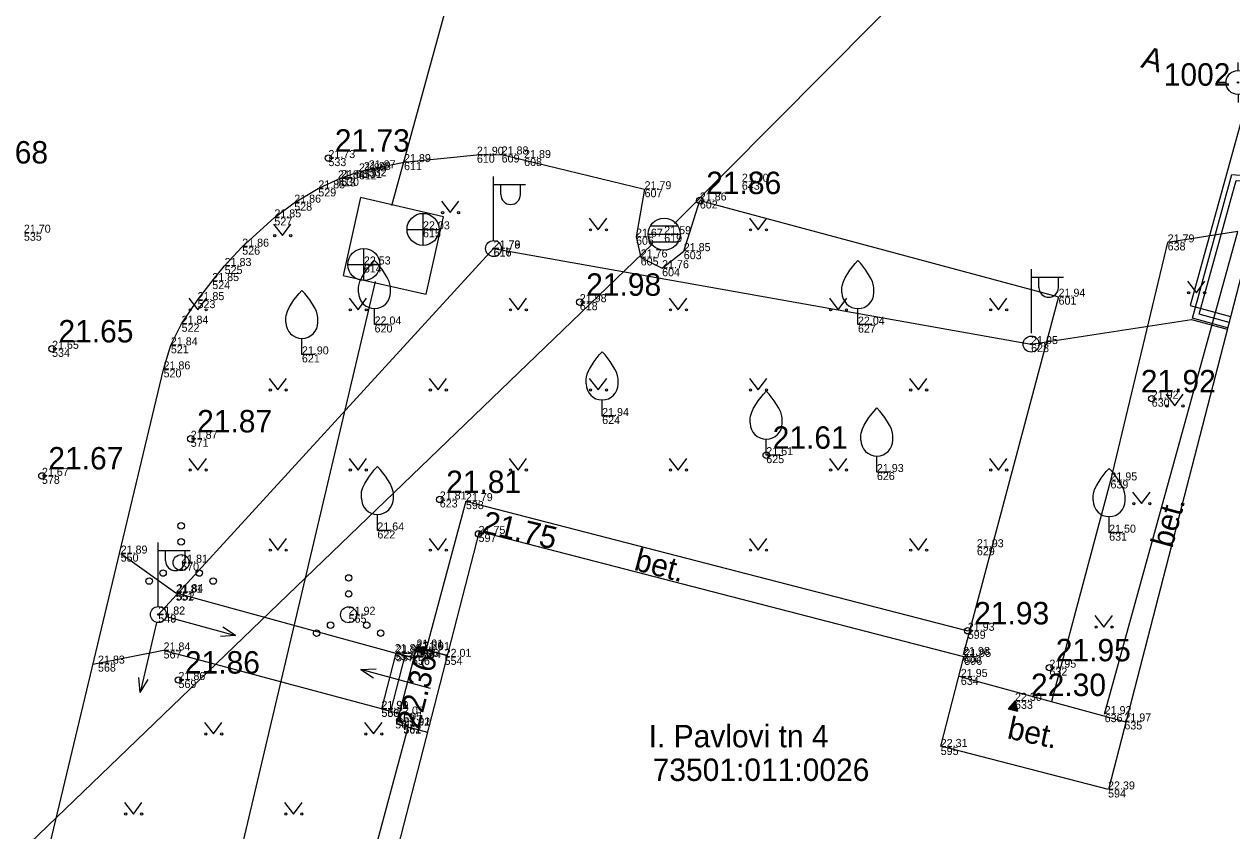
# Model space of a CAD drawing. Extents: x 714279 to 714471, y 6589851 to 6590083.
# Drawn here: x 714335.18 to 714372.9, y 6590005.81 to 6590030.99 of the extents above; entities that cross this region are included whole.
import ezdxf

# ---------------------------------------------------------------- set-up
doc = ezdxf.new("R2010")
doc.units = 0
for name, color, linetype in [('ALUSVORK', 7, 'Continuous'), ('HALJASTUS', 7, 'Continuous'), ('HOONE', 7, 'Continuous'), ('HOONEDET', 7, 'Continuous'), ('KKAEV', 7, 'Continuous'), ('KORGUS', 7, 'Continuous'), ('MOOTKORG', 7, 'Continuous'), ('MOOTMPUNKT', 7, 'Continuous'), ('MPKAABEL', 7, 'Continuous'), ('MPOHULIIN', 7, 'Continuous'), ('PIIR', 7, 'Continuous'), ('POST', 7, 'Continuous'), ('PUU', 7, 'Continuous'), ('SITRASS', 7, 'Continuous'), ('SKKAEV', 7, 'Continuous'), ('SKTRASS', 7, 'Continuous'), ('TEE', 7, 'Continuous'), ('TTRASS', 7, 'Continuous')]:
    doc.layers.add(name, color=color, linetype=linetype)

# ---------------------------------------------------------------- blocks, each defined once
blk = doc.blocks.new('SPYMAR')
at = {"layer": 'ALUSVORK'}
for p, q in [((0, 0.75), (0, 1.25)), ((-0.75, 0), (-1.25, 0)), ((0.75, 0), (1.25, 0)), ((0, -0.75), (0, -1.25))]:
    blk.add_line(p, q, dxfattribs=at)
for radius in [0.75, 0.044]:
    blk.add_circle((0, 0), radius, dxfattribs=at)
blk = doc.blocks.new('RING02')
at = {"layer": 'KORGUS'}
blk.add_circle((0, 0), 0.2, dxfattribs=at)
blk = doc.blocks.new('BEPOST')
at = {"layer": 'POST'}
for radius in [0.5, 0.0467]:
    blk.add_circle((0, 0), radius, dxfattribs=at)
blk = doc.blocks.new('POINT_DISPLAY')
blk.add_line((0, 0), (0, 0))
blk = doc.blocks.new('VAPOST')
at = {"layer": 'POST'}
for p, q in [((0, 0.5), (0, 4.5)), ((0, 4), (2, 4)), ((0.453, 3.358), (0.453, 4)), ((1.679, 3.358), (1.679, 4))]:
    blk.add_line(p, q, dxfattribs=at)
blk.add_arc((1.066, 3.358), 0.613, 180, 0, dxfattribs=at)
blk.add_blockref('POINT_DISPLAY', (0, 0), dxfattribs=at)
blk = doc.blocks.new('RTKQRG')
at = {"layer": 'HOONEDET'}
for p, q in [((0, 0), (-0.49, 0.97)), ((0.49, 0.97), (-0.49, 0.97)), ((-0.48, 0.94), (0.21, 0.42)), ((-0.44, 0.97), (0.23, 0.46)), ((-0.42, 0.84), (0.19, 0.37)), ((-0.37, 0.74), (0.17, 0.33)), ((-0.35, 0.97), (0.26, 0.51)), ((-0.32, 0.63), (0.14, 0.28)), ((-0.27, 0.97), (0.28, 0.55)), ((-0.27, 0.53), (0.12, 0.24)), ((-0.22, 0.43), (0.1, 0.19)), ((-0.19, 0.97), (0.3, 0.6)), ((-0.17, 0.33), (0.07, 0.15)), ((-0.11, 0.97), (0.33, 0.64)), ((-0.11, 0.22), (0.05, 0.1)), ((-0.06, 0.12), (0.03, 0.05)), ((-0.02, 0.97), (0.35, 0.69)), ((-0.01, 0.02), (0, 0.01)), ((0, 0), (0.49, 0.97)), ((0.06, 0.97), (0.37, 0.73)), ((0.14, 0.97), (0.39, 0.78)), ((0.22, 0.97), (0.42, 0.83)), ((0.31, 0.97), (0.44, 0.87)), ((0.39, 0.97), (0.46, 0.92)), ((0.47, 0.97), (0.49, 0.96))]:
    blk.add_line(p, q, dxfattribs=at)
blk = doc.blocks.new('VQSA')
at = {"layer": 'HALJASTUS'}
for centre, radius in [((0, 2.3), 0.2), ((0, 1.3), 0.2), ((0, 0), 0.5), ((-1.13, -0.65), 0.2), ((1.13, -0.65), 0.2), ((-2, -1.15), 0.2), ((2, -1.15), 0.2)]:
    blk.add_circle(centre, radius, dxfattribs=at)
blk = doc.blocks.new('KAKAEV')
at = {"layer": 'KKAEV'}
for p, q in [((0, -1), (0, 1)), ((-1, 0), (1, 0))]:
    blk.add_line(p, q, dxfattribs=at)
blk.add_circle((0, 0), 1, dxfattribs=at)
blk = doc.blocks.new('REKAEV')
at = {"layer": 'SKKAEV'}
for p, q in [((0.86, 0.5), (-0.86, 0.5)), ((-1, 0), (1, 0)), ((0.86, -0.5), (-0.86, -0.5))]:
    blk.add_line(p, q, dxfattribs=at)
blk.add_circle((0, 0), 1, dxfattribs=at)
blk = doc.blocks.new('VILJA1')
at = {"layer": 'PUU'}
for p, q in [((0, 0), (0, 1)), ((0.8, 0), (0, 0))]:
    blk.add_line(p, q, dxfattribs=at)
for points in [[(-1, 2), (-1, 2.3), (-0.98, 2.43), (-0.91, 2.69), (-0.79, 2.93), (-0.5, 3.4), (-0.18, 3.81), (0, 4)], [(1, 2), (1, 2.3), (0.98, 2.43), (0.91, 2.69), (0.79, 2.93), (0.5, 3.4), (0.18, 3.81), (0, 4)]]:
    blk.add_lwpolyline(points, dxfattribs=at)
blk.add_arc((0, 2), 1, 180, 0, dxfattribs=at)
blk = doc.blocks.new('MPSUUN')
at = {"layer": 'MPOHULIIN'}
for p, q in [((0.5, 0), (5, 0)), ((5, 0), (4.097, -0.297)), ((5, 0), (4.098, 0.3))]:
    blk.add_line(p, q, dxfattribs=at)
blk.add_blockref('POINT_DISPLAY', (0, 0), dxfattribs=at)
blk = doc.blocks.new('MURU_1')
at = {"layer": 'HALJASTUS'}
for p, q in [((-0.93, 1.21), (0, 0)), ((0, 0), (0.89, 1.21))]:
    blk.add_line(p, q, dxfattribs=at)
for centre in [(-0.8, 0), (0.86, 0)]:
    blk.add_circle(centre, 0.11, dxfattribs=at)

msp = doc.modelspace()

# ---------------------------------------------------------------- linework, layer by layer
at = {"layer": 'HOONE'}
for points in [[(714368.084, 6590003.497), (714362.833, 6589983.153), (714366.948, 6589982.091), (714366.479, 6589980.273), (714368.704, 6589979.699), (714369.168, 6589981.497), (714375.054, 6589979.978), (714385.707, 6590021.254), (714379.88, 6590022.758), (714380.346, 6590024.563), (714378.09, 6590025.145), (714377.63, 6590023.366), (714373.521, 6590024.426), (714369.05, 6590007.103), (714363.815, 6590008.455), (714364.534, 6590011.243), (714349.394, 6590015.151), (714346.235, 6590002.913), (714361.396, 6589999), (714362.901, 6590004.835), (714368.084, 6590003.497)], [(714347.349, 6590011.208), (714346.794, 6590011.353), (714346.34, 6590009.617), (714346.895, 6590009.472)], [(714347.075, 6590011.28), (714346.621, 6590009.544)], [(714346.794, 6590011.353), (714347.349, 6590011.208), (714347.434, 6590011.532), (714348.395, 6590011.281)], [(714348.395, 6590011.281), (714347.434, 6590011.532), (714346.811, 6590009.148), (714347.779, 6590008.895)], [(714364.436, 6590010.614), (714364.371, 6590010.632)], [(714364.436, 6590010.614), (714369.544, 6590009.225), (714369.589, 6590009.213), (714369.589, 6590009.213), (714369.589, 6590009.213)]]:
    msp.add_lwpolyline(points, dxfattribs=at)
at = {"layer": 'HOONEDET'}
for p, q in [((714366.128, 6590009.868), (714365.918, 6590009.617)), ((714366.195, 6590009.594), (714366.048, 6590009.772)), ((714366.187, 6590009.628), (714366.058, 6590009.784)), ((714366.179, 6590009.661), (714366.067, 6590009.795)), ((714366.171, 6590009.694), (714366.077, 6590009.807)), ((714366.163, 6590009.728), (714366.087, 6590009.819)), ((714366.154, 6590009.761), (714366.097, 6590009.831)), ((714366.146, 6590009.795), (714366.107, 6590009.842)), ((714366.138, 6590009.828), (714366.116, 6590009.854)), ((714366.13, 6590009.861), (714366.126, 6590009.866)), ((714366.128, 6590009.868), (714366.206, 6590009.55)), ((714365.918, 6590009.617), (714366.206, 6590009.55)), ((714365.925, 6590009.615), (714365.921, 6590009.62)), ((714365.949, 6590009.61), (714365.931, 6590009.631)), ((714365.973, 6590009.604), (714365.94, 6590009.643)), ((714365.997, 6590009.598), (714365.95, 6590009.655)), ((714366.021, 6590009.593), (714365.96, 6590009.667)), ((714366.045, 6590009.587), (714365.97, 6590009.678)), ((714366.069, 6590009.582), (714365.979, 6590009.69)), ((714366.094, 6590009.576), (714365.989, 6590009.702)), ((714366.118, 6590009.571), (714365.999, 6590009.713)), ((714366.142, 6590009.565), (714366.009, 6590009.725)), ((714366.166, 6590009.559), (714366.019, 6590009.737)), ((714366.19, 6590009.554), (714366.028, 6590009.749)), ((714366.204, 6590009.561), (714366.038, 6590009.76))]:
    msp.add_line(p, q, dxfattribs=at)
at = {"layer": 'KORGUS'}
for centre in [(714356.285, 6590025.488), (714352.536, 6590022.313), (714370.398, 6590019.3), (714358.36, 6590017.538), (714348.163, 6590016.155), (714349.375, 6590015.078), (714364.653, 6590012.055), (714367.203, 6590010.903)]:
    msp.add_circle(centre, 0.1, dxfattribs=at)
at = {"layer": 'MPKAABEL'}
for points in [[(714372.768, 6590021.51), (714371.67, 6590021.813), (714372.903, 6590026.299), (714377.515, 6590025.926), (714382.377, 6590024.932), (714383.808, 6590025.49), (714388.238, 6590038.714), (714390.005, 6590045.675), (714389.318, 6590046.817), (714361.052, 6590054.85), (714347.71, 6590058.063), (714329.047, 6590059.566), (714322.309, 6590060.484), (714316.991, 6590061.578)], [(714372.812, 6590021.678), (714371.882, 6590021.934), (714373.032, 6590026.115), (714377.491, 6590025.755), (714382.392, 6590024.752), (714383.947, 6590025.358), (714388.404, 6590038.665), (714390.19, 6590045.703), (714389.431, 6590046.965), (714361.096, 6590055.017), (714347.738, 6590058.234), (714329.065, 6590059.739), (714322.338, 6590060.654), (714317.026, 6590061.747)], [(714339.376, 6590012.563), (714349.845, 6590023.988), (714366.632, 6590021.005), (714371.641, 6590021.777)], [(714371.641, 6590021.777), (714372.758, 6590021.475)]]:
    msp.add_lwpolyline(points, dxfattribs=at)
at = {"layer": 'SITRASS'}
msp.add_lwpolyline([(714320.359, 6590061.207), (714337.402, 6590059.587), (714379.185, 6590049.636), (714371.595, 6590022.212), (714372.86, 6590021.865)], dxfattribs=at)
at = {"layer": 'SKTRASS'}
for points in [[(714355.498, 6590024.768), (714385.19, 6590054.667)], [(714320.65, 6589991.283), (714354.787, 6590024.118)]]:
    msp.add_lwpolyline(points, dxfattribs=at)
at = {"layer": 'TEE'}
for points in [[(714335.261, 6590002.325), (714339.537, 6590020.216), (714339.765, 6590020.967), (714340.101, 6590021.64), (714340.598, 6590022.377), (714341.058, 6590022.972), (714341.445, 6590023.444), (714341.994, 6590024.046), (714342.998, 6590024.961), (714343.618, 6590025.42), (714344.37, 6590025.865), (714345.081, 6590026.191), (714345.734, 6590026.417), (714347.047, 6590026.686), (714349.323, 6590026.917), (714350.096, 6590026.925), (714354.559, 6590025.84), (714354.292, 6590024.356), (714354.438, 6590023.71), (714355.107, 6590023.373), (714355.784, 6590023.906), (714356.285, 6590025.488), (714367.488, 6590022.485), (714364.507, 6590011.301)], [(714368.928, 6590009.453), (714373.082, 6590024.523), (714370.895, 6590024.179), (714369.109, 6590016.749), (714367.271, 6590009.843)], [(714348.98, 6590016.103), (714348.98, 6590016.103), (714347.729, 6590011.455)], [(714348.98, 6590016.103), (714364.653, 6590012.055)], [(714338.198, 6590014.465), (714339.919, 6590013.244)], [(714339.919, 6590013.244), (714346.794, 6590011.353)], [(714346.345, 6590009.617), (714339.537, 6590011.441), (714337.331, 6590011.003)], [(714361.809, 6589998.014), (714354.213, 6589999.987), (714345.378, 6590002.344), (714347.181, 6590009.051)]]:
    msp.add_lwpolyline(points, dxfattribs=at)
at = {"layer": 'TTRASS'}
for points in [[(714348.353, 6590031.495), (714346.654, 6590025.325)], [(714345.69, 6590025.577), (714345.146, 6590023.146), (714347.595, 6590022.598), (714347.741, 6590022.565), (714348.281, 6590024.982), (714345.69, 6590025.577)], [(714346.146, 6590022.954), (714339.047, 6589992.888), (714362.991, 6589983.765)]]:
    msp.add_lwpolyline(points, dxfattribs=at)

# ---------------------------------------------------------------- block references
at = {"layer": 'ALUSVORK', "xscale": 0.5, "yscale": 0.5}
msp.add_blockref('SPYMAR', (714373.093, 6590029.172), dxfattribs=at)
at = {"layer": 'HALJASTUS'}
for name, p, xscale, yscale in [('MURU_1', (714348.493, 6590025.108), 0.3, 0.3), ('MURU_1', (714353.11, 6590024.573), 0.3, 0.3), ('MURU_1', (714358.11, 6590024.573), 0.3, 0.3), ('MURU_1', (714343.249, 6590024.391), 0.3, 0.3), ('MURU_1', (714371.793, 6590022.608), 0.3, 0.3), ('MURU_1', (714340.61, 6590022.073), 0.3, 0.3), ('MURU_1', (714345.61, 6590022.073), 0.3, 0.3), ('MURU_1', (714350.61, 6590022.073), 0.3, 0.3), ('MURU_1', (714355.61, 6590022.073), 0.3, 0.3), ('MURU_1', (714360.61, 6590022.073), 0.3, 0.3), ('MURU_1', (714365.61, 6590022.073), 0.3, 0.3), ('MURU_1', (714343.11, 6590019.573), 0.3, 0.3), ('MURU_1', (714348.11, 6590019.573), 0.3, 0.3), ('MURU_1', (714353.11, 6590019.573), 0.3, 0.3), ('MURU_1', (714358.11, 6590019.573), 0.3, 0.3), ('MURU_1', (714363.11, 6590019.573), 0.3, 0.3), ('MURU_1', (714371.115, 6590019.074), 0.3, 0.3), ('MURU_1', (714340.61, 6590017.073), 0.3, 0.3), ('MURU_1', (714345.61, 6590017.073), 0.3, 0.3), ('MURU_1', (714350.61, 6590017.073), 0.3, 0.3), ('MURU_1', (714355.61, 6590017.073), 0.3, 0.3), ('MURU_1', (714360.61, 6590017.073), 0.3, 0.3), ('MURU_1', (714365.61, 6590017.073), 0.3, 0.3), ('MURU_1', (714370.078, 6590016.024), 0.3, 0.3), ('VQSA', (714340.087, 6590014.182), 0.5, 0.5), ('MURU_1', (714343.11, 6590014.573), 0.3, 0.3), ('MURU_1', (714348.11, 6590014.573), 0.3, 0.3), ('MURU_1', (714358.11, 6590014.573), 0.3, 0.3), ('MURU_1', (714363.11, 6590014.573), 0.3, 0.3), ('VQSA', (714345.317, 6590012.556), 0.5, 0.5), ('MURU_1', (714368.901, 6590012.171), 0.3, 0.3), ('MURU_1', (714341.095, 6590008.834), 0.3, 0.3), ('MURU_1', (714346.095, 6590008.834), 0.3, 0.3), ('MURU_1', (714338.595, 6590006.334), 0.3, 0.3), ('MURU_1', (714343.595, 6590006.334), 0.3, 0.3)]:
    msp.add_blockref(name, p, dxfattribs=dict(at, xscale=xscale, yscale=yscale))
at = {"layer": 'HOONEDET', "xscale": 0.3, "yscale": 0.29999999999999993, "rotation": -112.13738709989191}
msp.add_blockref('RTKQRG', (714347.43, 6590011.533), dxfattribs=at)
at = {"layer": 'KKAEV', "xscale": 0.5, "yscale": 0.5}
for p in [(714347.64, 6590024.587), (714345.792, 6590023.49)]:
    msp.add_blockref('KAKAEV', p, dxfattribs=at)
at = {"layer": 'KORGUS', "xscale": 0.5, "yscale": 0.5}
for p in [(714344.686, 6590026.812), (714336.055, 6590020.857), (714340.386, 6590018.048), (714335.739, 6590016.891), (714340.004, 6590010.519)]:
    msp.add_blockref('RING02', p, dxfattribs=at)
at = {"layer": 'MPOHULIIN'}
for p, xscale, yscale, rotation in [((714339.373, 6590012.562), 0.49999999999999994, 0.5000000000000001, -103.15639783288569), ((714339.373, 6590012.562), 0.5, 0.5, -15.204134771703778), ((714348.114, 6590010.191), 0.49999999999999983, 0.4999999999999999, 164.81101962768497)]:
    msp.add_blockref('MPSUUN', p, dxfattribs=dict(at, xscale=xscale, yscale=yscale, rotation=rotation))
at = {"layer": 'POST', "xscale": 0.5, "yscale": 0.5}
for name, p in [('VAPOST', (714349.843, 6590023.991)), ('BEPOST', (714349.845, 6590023.988)), ('VAPOST', (714366.646, 6590021.096)), ('BEPOST', (714366.632, 6590021.005)), ('VAPOST', (714339.373, 6590012.562)), ('BEPOST', (714339.376, 6590012.563))]:
    msp.add_blockref(name, p, dxfattribs=at)
at = {"layer": 'PUU', "xscale": 0.5, "yscale": 0.5}
for p in [(714346.127, 6590021.618), (714361.223, 6590021.612), (714343.858, 6590020.683), (714353.235, 6590018.76), (714358.36, 6590017.538), (714361.815, 6590017.01), (714346.214, 6590015.187), (714369.068, 6590015.118)]:
    msp.add_blockref('VILJA1', p, dxfattribs=at)
at = {"layer": 'SKKAEV', "xscale": 0.5, "yscale": 0.5}
msp.add_blockref('REKAEV', (714355.173, 6590024.436), dxfattribs=at)

# ---------------------------------------------------------------- texts
at = {"layer": 'ALUSVORK'}
msp.add_text('1002', height=0.7, dxfattribs=at).set_placement((714370.772, 6590029.072))
at = {"layer": 'HOONEDET'}
msp.add_text('22.36', height=0.7, rotation=75.8721, dxfattribs=at).set_placement((714347.511, 6590008.955))
msp.add_text('22.30', height=0.7, dxfattribs=at).set_placement((714366.628, 6590010.018))
at = {"layer": 'KORGUS'}
for s, p in [('21.73', (714344.886, 6590027.012)), ('21.68', (714333.589, 6590026.642)), ('21.86', (714356.485, 6590025.688)), ('21.98', (714352.736, 6590022.513)), ('21.65', (714336.255, 6590021.057)), ('21.92', (714370.056, 6590019.5)), ('21.87', (714340.586, 6590018.248)), ('21.61', (714358.56, 6590017.738)), ('21.67', (714335.939, 6590017.091)), ('21.81', (714348.363, 6590016.355)), ('21.93', (714364.853, 6590012.255)), ('21.95', (714367.403, 6590011.103)), ('21.86', (714340.204, 6590010.719))]:
    msp.add_text(s, height=0.7, dxfattribs=at).set_placement(p)
msp.add_text('21.75', height=0.7, rotation=346.7042, dxfattribs=at).set_placement((714349.446, 6590015.129))
at = {"layer": 'MOOTKORG'}
for s, p in [('21.90', (714349.323, 6590026.917)), ('21.88', (714350.096, 6590026.925)), ('21.73', (714344.686, 6590026.812)), ('21.87', (714345.946, 6590026.493)), ('21.89', (714347.047, 6590026.686)), ('21.89', (714350.798, 6590026.813)), ('21.84', (714344.983, 6590026.177)), ('21.86', (714345.081, 6590026.191)), ('21.86', (714345.638, 6590026.397)), ('21.88', (714345.796, 6590026.439)), ('21.85', (714344.37, 6590025.865)), ('21.79', (714354.559, 6590025.84)), ('21.70', (714357.598, 6590026.074)), ('21.86', (714343.618, 6590025.42)), ('21.86', (714356.285, 6590025.488)), ('21.85', (714342.998, 6590024.961)), ('21.70', (714335.175, 6590024.482)), ('22.03', (714347.64, 6590024.587)), ('21.67', (714354.292, 6590024.356)), ('21.59', (714355.173, 6590024.436)), ('21.86', (714341.994, 6590024.046)), ('21.78', (714349.843, 6590023.991)), ('21.79', (714349.845, 6590023.988)), ('21.85', (714355.784, 6590023.906)), ('21.79', (714370.895, 6590024.179)), ('22.53', (714345.792, 6590023.49)), ('21.76', (714354.438, 6590023.71)), ('21.83', (714341.445, 6590023.444)), ('21.76', (714355.107, 6590023.373)), ('21.85', (714341.058, 6590022.972)), ('21.85', (714340.598, 6590022.377)), ('21.94', (714367.488, 6590022.485)), ('21.98', (714352.536, 6590022.313)), ('21.84', (714340.101, 6590021.64)), ('22.04', (714346.127, 6590021.618)), ('22.04', (714361.223, 6590021.612)), ('21.65', (714336.055, 6590020.857)), ('21.84', (714339.765, 6590020.967)), ('21.95', (714366.632, 6590021.005)), ('21.90', (714343.858, 6590020.683)), ('21.86', (714339.537, 6590020.216)), ('21.92', (714370.398, 6590019.3)), ('21.94', (714353.235, 6590018.76)), ('21.87', (714340.386, 6590018.048)), ('21.61', (714358.36, 6590017.538)), ('21.67', (714335.739, 6590016.891)), ('21.93', (714361.815, 6590017.01)), ('21.95', (714369.109, 6590016.749)), ('21.81', (714348.163, 6590016.155)), ('21.79', (714348.98, 6590016.103)), ('21.64', (714346.214, 6590015.187)), ('21.75', (714349.375, 6590015.078)), ('21.50', (714369.068, 6590015.118)), ('21.89', (714338.198, 6590014.465)), ('21.93', (714364.938, 6590014.663)), ('21.81', (714340.087, 6590014.182)), ('21.81', (714339.919, 6590013.244)), ('21.84', (714339.947, 6590013.261)), ('21.82', (714339.373, 6590012.562)), ('21.82', (714339.376, 6590012.563)), ('21.92', (714345.317, 6590012.556)), ('21.93', (714364.653, 6590012.055)), ('21.84', (714339.537, 6590011.441)), ('21.91', (714347.434, 6590011.532)), ('22.36', (714347.435, 6590011.47)), ('21.91', (714347.642, 6590011.451)), ('21.83', (714337.49, 6590011.03)), ('21.88', (714346.757, 6590011.39)), ('21.91', (714346.794, 6590011.353)), ('21.96', (714347.296, 6590011.242)), ('22.01', (714348.315, 6590011.242)), ('21.98', (714364.507, 6590011.301)), ('21.95', (714364.545, 6590011.24)), ('21.95', (714367.203, 6590010.903)), ('21.86', (714340.004, 6590010.519)), ('21.95', (714364.436, 6590010.614)), ('21.91', (714346.34, 6590009.617)), ('21.90', (714346.345, 6590009.617)), ('22.30', (714366.128, 6590009.868)), ('21.95', (714346.773, 6590009.257)), ('22.07', (714346.83, 6590009.44)), ('21.92', (714368.928, 6590009.453)), ('21.97', (714369.544, 6590009.225)), ('21.92', (714347.026, 6590009.092)), ('21.91', (714347.029, 6590009.105)), ('22.31', (714363.808, 6590008.429)), ('22.39', (714369.035, 6590007.102))]:
    msp.add_text(s, height=0.25, dxfattribs=at).set_placement(p)
at = {"layer": 'MOOTMPUNKT'}
for s, p in [('533', (714344.686, 6590026.562)), ('610', (714349.323, 6590026.667)), ('609', (714350.096, 6590026.675)), ('608', (714350.798, 6590026.563)), ('612', (714345.638, 6590026.147)), ('531', (714345.796, 6590026.189)), ('532', (714345.946, 6590026.243)), ('611', (714347.047, 6590026.436)), ('613', (714344.983, 6590025.927)), ('530', (714345.081, 6590025.941)), ('643', (714357.598, 6590025.824)), ('529', (714344.37, 6590025.615)), ('607', (714354.559, 6590025.59)), ('528', (714343.618, 6590025.17)), ('602', (714356.285, 6590025.238)), ('527', (714342.998, 6590024.711)), ('535', (714335.175, 6590024.232)), ('615', (714347.64, 6590024.337)), ('606', (714354.292, 6590024.106)), ('619', (714355.173, 6590024.186)), ('638', (714370.895, 6590023.929)), ('526', (714341.994, 6590023.796)), ('617', (714349.843, 6590023.741)), ('616', (714349.845, 6590023.738)), ('603', (714355.784, 6590023.656)), ('525', (714341.445, 6590023.194)), ('614', (714345.792, 6590023.24)), ('605', (714354.438, 6590023.46)), ('604', (714355.107, 6590023.123)), ('524', (714341.058, 6590022.722)), ('523', (714340.598, 6590022.127)), ('618', (714352.536, 6590022.063)), ('601', (714367.488, 6590022.235)), ('522', (714340.101, 6590021.39)), ('620', (714346.127, 6590021.368)), ('627', (714361.223, 6590021.362)), ('534', (714336.055, 6590020.607)), ('521', (714339.765, 6590020.717)), ('628', (714366.632, 6590020.755)), ('621', (714343.858, 6590020.433)), ('520', (714339.537, 6590019.966)), ('630', (714370.398, 6590019.05)), ('624', (714353.235, 6590018.51)), ('571', (714340.386, 6590017.798)), ('625', (714358.36, 6590017.288)), ('626', (714361.815, 6590016.76)), ('578', (714335.739, 6590016.641)), ('639', (714369.109, 6590016.499)), ('623', (714348.163, 6590015.905)), ('598', (714348.98, 6590015.853)), ('622', (714346.214, 6590014.937)), ('597', (714349.375, 6590014.828)), ('631', (714369.068, 6590014.868)), ('629', (714364.938, 6590014.413)), ('550', (714338.198, 6590014.215)), ('570', (714340.087, 6590013.932)), ('551', (714339.919, 6590012.994)), ('552', (714339.947, 6590013.011)), ('549', (714339.373, 6590012.312)), ('548', (714339.376, 6590012.313)), ('565', (714345.317, 6590012.306)), ('599', (714364.653, 6590011.805)), ('567', (714339.537, 6590011.191)), ('553', (714346.757, 6590011.14)), ('557', (714346.794, 6590011.103)), ('555', (714347.434, 6590011.282)), ('563', (714347.435, 6590011.22)), ('564', (714347.642, 6590011.201)), ('600', (714364.507, 6590011.051)), ('568', (714337.49, 6590010.78)), ('556', (714347.296, 6590010.992)), ('554', (714348.315, 6590010.992)), ('596', (714364.545, 6590010.99)), ('632', (714367.203, 6590010.653)), ('569', (714340.004, 6590010.269)), ('634', (714364.436, 6590010.364)), ('633', (714366.128, 6590009.618)), ('558', (714346.34, 6590009.367)), ('566', (714346.345, 6590009.367)), ('559', (714346.83, 6590009.19)), ('636', (714368.928, 6590009.203)), ('560', (714346.773, 6590009.007)), ('561', (714347.026, 6590008.842)), ('562', (714347.029, 6590008.855)), ('635', (714369.544, 6590008.975)), ('595', (714363.808, 6590008.179)), ('594', (714369.035, 6590006.852))]:
    msp.add_text(s, height=0.25, dxfattribs=at).set_placement(p)
at = {"layer": 'PIIR'}
for s, p in [('I. Pavlovi tn 4', (714354.687, 6590008.416)), ('73501:011:0026', (714354.812, 6590007.367))]:
    msp.add_text(s, height=0.7, dxfattribs=at).set_placement(p)
at = {"layer": 'TEE'}
for s, rotation, p in [('A', 343.7603, (714370.031, 6590029.653)), ('bet.', 74.6556, (714371.036, 6590014.608)), ('bet.', 345.2137, (714354.2, 6590013.963)), ('bet.', 347.5999, (714365.856, 6590008.705))]:
    msp.add_text(s, height=0.7, rotation=rotation, dxfattribs=at).set_placement(p)

doc.saveas('drawing.dxf')
